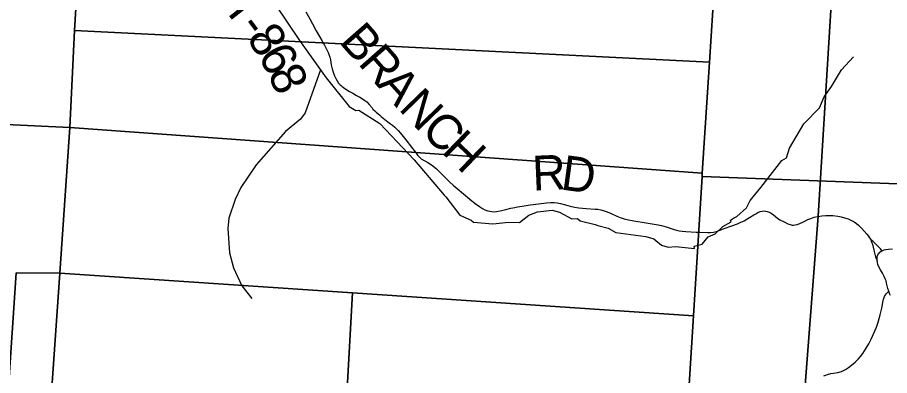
# Model space of a CAD drawing. Extents: x 0 to 34, y 0 to 22.
# Drawn here: x 27.11 to 28.533, y 17.075 to 17.66 of the extents above; entities that cross this region are included whole.
import ezdxf

# ---------------------------------------------------------------- set-up
doc = ezdxf.new("R2010")
doc.units = 0
for name, color, linetype in [('GM_X_County_Road', 7, 'Continuous'), ('GM_X_County_Text', 7, 'Continuous'), ('GM_X_Minor_River', 7, 'Continuous'), ('GM_X_Section', 7, 'Continuous'), ('GM_X_Township_Road', 7, 'Continuous'), ('GM_X_Township_Road_Text', 7, 'Continuous')]:
    doc.layers.add(name, color=color, linetype=linetype)

msp = doc.modelspace()

# ---------------------------------------------------------------- linework, layer by layer
at = {"layer": 'GM_X_County_Road'}
for points in [[(28.5341, 17.2061), (28.5326, 17.2093), (28.5312, 17.2132), (28.5299, 17.2173), (28.5288, 17.222), (28.5278, 17.2264), (28.5268, 17.23), (28.5256, 17.2333), (28.5239, 17.2371), (28.5211, 17.2426), (28.518, 17.2482), (28.5151, 17.2531), (28.5137, 17.2567), (28.5127, 17.2597), (28.5123, 17.2639), (28.5123, 17.2662), (28.5126, 17.2686), (28.513, 17.2708), (28.5136, 17.2722), (28.5146, 17.2739), (28.5158, 17.2754), (28.5169, 17.2767), (28.5184, 17.2779), (28.52, 17.2788), (28.5216, 17.2797), (28.5237, 17.2804), (28.5267, 17.2811), (28.5309, 17.2817), (28.5371, 17.2823)], [(28.4255, 17.0749), (28.4288, 17.0763), (28.4312, 17.0772), (28.4365, 17.0786), (28.4412, 17.0795), (28.4481, 17.0805), (28.4541, 17.0823), (28.4576, 17.0839), (28.4609, 17.0856), (28.4656, 17.0887), (28.4706, 17.0925), (28.4763, 17.0974), (28.4812, 17.1021), (28.4854, 17.1068), (28.4888, 17.1113), (28.4946, 17.1201), (28.4988, 17.1271), (28.5028, 17.1349), (28.5071, 17.1445), (28.5111, 17.1543), (28.514, 17.1625), (28.5158, 17.1685), (28.5174, 17.1745), (28.5197, 17.1855), (28.5223, 17.1979), (28.5229, 17.2003), (28.5236, 17.2026), (28.5243, 17.2043), (28.5252, 17.206), (28.5262, 17.2074), (28.5273, 17.2088), (28.5312, 17.2132)]]:
    msp.add_lwpolyline(points, dxfattribs=at)
at = {"layer": 'GM_X_County_Text'}
for points in [[(27.0716, 14.2873), (27.1862, 14.3829), (27.4012, 14.5633), (27.5003, 14.6738), (27.528, 14.7368), (27.5892, 14.8006), (27.6689, 14.9115), (27.8265, 15.0679), (27.967, 15.1616), (28.1376, 15.2493), (28.2671, 15.2953), (28.2799, 15.2948), (28.2867, 15.4004), (28.3527, 16.4269), (28.3944, 17.0528), (28.4159, 17.3358), (28.4427, 17.7695)], [(28.4427, 17.7695), (28.4159, 17.3358), (28.3944, 17.0528), (28.3527, 16.4269), (28.2867, 15.4004), (28.2799, 15.2948), (28.3301, 15.293), (28.3692, 15.2637), (28.4182, 15.3245), (28.4801, 15.3522), (28.6571, 15.3822), (28.9104, 15.3867), (29.0987, 15.3975), (29.1238, 15.3963), (29.3286, 15.3596), (29.3112, 15.3354), (29.211, 15.3094), (29.213, 15.295), (29.3097, 15.2479), (29.423, 15.2518), (29.4264, 15.2648), (29.4018, 15.2725), (29.4304, 15.2876), (29.5713, 15.2568)]]:
    msp.add_lwpolyline(points, dxfattribs=at)
at = {"layer": 'GM_X_Minor_River'}
for points in [[(27.5304, 17.6805), (27.5698, 17.6221), (27.6133, 17.5614), (27.6508, 17.5147), (27.6618, 17.5079), (27.6667, 17.5083), (27.7011, 17.4867), (27.7571, 17.4275), (27.8059, 17.3699), (27.8086, 17.3672), (27.8313, 17.3373), (27.8498, 17.3289), (27.8536, 17.3259), (27.885, 17.3229), (27.9114, 17.3257), (27.9288, 17.3253), (27.9439, 17.3371), (27.9583, 17.3425), (27.9821, 17.3452), (27.9938, 17.3422), (28.0142, 17.3312), (28.0233, 17.3316), (28.0278, 17.3278), (28.0524, 17.3218), (28.0566, 17.3203), (28.0736, 17.3161), (28.0857, 17.309), (28.1348, 17.3026), (28.1481, 17.2988), (28.1606, 17.2882), (28.1712, 17.2852), (28.1836, 17.286), (28.2142, 17.283), (28.2135, 17.2864), (28.2267, 17.2899), (28.2365, 17.3021), (28.2482, 17.3067), (28.2603, 17.3185), (28.2739, 17.3261), (28.2732, 17.3291), (28.2781, 17.3322), (28.2834, 17.3352), (28.2989, 17.3493), (28.3049, 17.3611), (28.3223, 17.3821), (28.357, 17.4262), (28.3642, 17.4308), (28.3691, 17.4468), (28.3925, 17.486), (28.4182, 17.5123), (28.4257, 17.5302), (28.4378, 17.5469), (28.454, 17.5743), (28.474, 17.5956)], [(27.6038, 17.5746), (27.5792, 17.5043), (27.5714, 17.4936), (27.5469, 17.4739), (27.4992, 17.4192), (27.4742, 17.3824), (27.4646, 17.363), (27.4546, 17.3325), (27.4526, 17.3155), (27.4555, 17.2759), (27.4623, 17.2514), (27.4758, 17.2221), (27.4918, 17.2011)]]:
    msp.add_lwpolyline(points, dxfattribs=at)
at = {"layer": 'GM_X_Section'}
for points in [[(26.2062, 18.5294), (27.254, 18.479), (27.228, 18.0601), (27.2029, 17.6387), (27.1952, 17.4804), (26.5953, 17.5088), (26.1481, 17.5351), (26.1482, 17.5386), (26.1578, 17.7173), (26.1806, 18.1307)], [(29.3481, 18.3713), (29.2849, 17.3606), (28.2266, 17.4004), (28.2269, 17.4056), (28.2386, 17.5871), (28.2659, 18.0119), (28.293, 18.4323)], [(28.2659, 18.0119), (28.2386, 17.5871), (27.2029, 17.6387), (27.228, 18.0601)], [(27.2029, 17.6387), (28.2386, 17.5871), (28.2269, 17.4056), (27.1952, 17.4804)], [(27.1952, 17.4804), (27.1786, 17.2427), (27.1074, 17.2433), (27.0684, 16.6654), (26.5448, 16.6908), (26.5953, 17.5088)], [(28.2269, 17.4056), (28.2266, 17.4004), (28.2124, 17.1731), (27.656, 17.2106), (27.1786, 17.2427), (27.1952, 17.4804)], [(28.2266, 17.4004), (29.2849, 17.3606), (29.2195, 16.3096), (29.0277, 16.3171), (28.8298, 16.3203), (28.6263, 16.3303), (28.4372, 16.34), (28.2749, 16.348), (28.1612, 16.354), (28.2124, 17.1731)], [(27.1786, 17.2427), (27.1198, 16.4014), (27.0508, 16.4046), (27.0684, 16.6654), (27.1074, 17.2433)], [(27.656, 17.2106), (27.6098, 16.3785), (27.1198, 16.4014), (27.1786, 17.2427)], [(28.2124, 17.1731), (28.1612, 16.354), (27.6098, 16.3785), (27.656, 17.2106)]]:
    msp.add_lwpolyline(points, close=True, dxfattribs=at)
at = {"layer": 'GM_X_Township_Road'}
for points in [[(27.5802, 17.6689), (27.5864, 17.6575), (27.5909, 17.6493), (27.5972, 17.6379), (27.6025, 17.6288), (27.6063, 17.6224), (27.6107, 17.6144), (27.6141, 17.6082), (27.6166, 17.6026), (27.6195, 17.595), (27.6206, 17.5908), (27.6217, 17.5825), (27.623, 17.5759), (27.6245, 17.5708), (27.6267, 17.5647), (27.629, 17.56), (27.6312, 17.5563), (27.6336, 17.5528), (27.636, 17.5501), (27.6376, 17.5486), (27.6396, 17.5469), (27.6435, 17.544), (27.6513, 17.5392), (27.6567, 17.5361), (27.6626, 17.5327), (27.668, 17.5296), (27.6744, 17.5259), (27.6766, 17.5245), (27.6794, 17.5219), (27.6832, 17.5177), (27.6881, 17.5121), (27.6897, 17.5103), (27.6929, 17.5073), (27.6951, 17.5052), (27.6984, 17.5024), (27.7007, 17.5004), (27.7031, 17.4984), (27.7059, 17.496), (27.7096, 17.4928), (27.7111, 17.4916), (27.714, 17.4893), (27.718, 17.4864), (27.7215, 17.4838), (27.7254, 17.4806), (27.7282, 17.4781), (27.7309, 17.4752), (27.7345, 17.471), (27.7412, 17.4631), (27.7434, 17.4601), (27.7524, 17.4482), (27.7584, 17.4405)], [(27.7584, 17.4405), (27.7596, 17.4389), (27.761, 17.4369), (27.7621, 17.4352), (27.7633, 17.4338), (27.7649, 17.4323), (27.7665, 17.4306), (27.7684, 17.4292), (27.7792, 17.4229), (27.7849, 17.4192), (27.7899, 17.4156), (27.7932, 17.4128), (27.7985, 17.4076), (27.8046, 17.4014), (27.8143, 17.3918), (27.8211, 17.3856), (27.8271, 17.3805), (27.8476, 17.3635), (27.8563, 17.3565), (27.8633, 17.3513), (27.8685, 17.348), (27.8724, 17.3461), (27.8771, 17.3443), (27.8801, 17.3435), (27.8837, 17.343), (27.8875, 17.3429), (27.8912, 17.3432), (27.8973, 17.3442), (27.9063, 17.3463), (27.9147, 17.3484), (27.9214, 17.3499), (27.9257, 17.3508), (27.933, 17.352), (27.9459, 17.3539), (27.9509, 17.3545), (27.973, 17.3572), (27.9799, 17.3577), (27.9854, 17.3577), (27.9904, 17.3572), (27.9959, 17.3562), (28.0037, 17.3542), (28.0115, 17.352), (28.0187, 17.3504), (28.0255, 17.3492), (28.0316, 17.3485), (28.0378, 17.348), (28.0521, 17.3472), (28.0564, 17.3468), (28.0613, 17.3458), (28.0667, 17.3444), (28.0719, 17.3425), (28.0782, 17.3398), (28.0878, 17.3354), (28.093, 17.3334), (28.0996, 17.3314), (28.1068, 17.3296), (28.1153, 17.3279), (28.1355, 17.3246), (28.1551, 17.3214), (28.1606, 17.3203), (28.1678, 17.3183), (28.1813, 17.3137), (28.1849, 17.3127), (28.1891, 17.3117), (28.194, 17.3109), (28.2002, 17.3103), (28.217, 17.3097), (28.2232, 17.3095), (28.2362, 17.3088), (28.2406, 17.3089), (28.2455, 17.3095), (28.2497, 17.3104), (28.2519, 17.3111), (28.2548, 17.3121), (28.2646, 17.3158), (28.2734, 17.3191), (28.2844, 17.3233), (28.2901, 17.3257), (28.2929, 17.327), (28.2951, 17.3281), (28.3015, 17.3318), (28.3042, 17.3334), (28.311, 17.3376), (28.3142, 17.3394), (28.3174, 17.3413), (28.3213, 17.3431), (28.3248, 17.3439), (28.3279, 17.3441), (28.3303, 17.3439), (28.3327, 17.3433), (28.3361, 17.3421), (28.3393, 17.3403), (28.3432, 17.3375), (28.3499, 17.3321), (28.3534, 17.3298), (28.3604, 17.3261), (28.3664, 17.3232), (28.3705, 17.3218), (28.3735, 17.3211), (28.3759, 17.321), (28.3783, 17.3212), (28.3819, 17.3221), (28.386, 17.3236), (28.3921, 17.3265), (28.3993, 17.3301), (28.4039, 17.3319), (28.4097, 17.3338), (28.4152, 17.335)], [(28.4152, 17.335), (28.4162, 17.3352), (28.4218, 17.3362), (28.4286, 17.3368), (28.4341, 17.3369), (28.4402, 17.3366), (28.4482, 17.3356), (28.4537, 17.3345), (28.459, 17.3331), (28.4649, 17.331), (28.4705, 17.3285), (28.4749, 17.3261), (28.4785, 17.3237), (28.4818, 17.3208), (28.4866, 17.316), (28.4909, 17.3113), (28.4953, 17.3063), (28.4981, 17.303), (28.5, 17.3003), (28.5018, 17.2976), (28.5028, 17.295), (28.5038, 17.2922), (28.5045, 17.2897), (28.5069, 17.28), (28.5089, 17.2716), (28.5103, 17.2676), (28.5123, 17.2639)], [(28.52, 17.2788), (28.5177, 17.2821), (28.5148, 17.285), (28.51, 17.29), (28.5055, 17.2945), (28.5037, 17.2961), (28.5018, 17.2976)]]:
    msp.add_lwpolyline(points, dxfattribs=at)

# ---------------------------------------------------------------- texts
at = {"layer": 'GM_X_Township_Road_Text'}
for s, rotation, p in [('T', 308.0554, (27.4429, 17.6773)), ('-', 306.8199, (27.4689, 17.6441)), ('8', 303.4072, (27.4824, 17.6261)), ('B', 311.3477, (27.6331, 17.6197)), ('R', 311.3464, (27.6639, 17.5846)), ('6', 298.8464, (27.5011, 17.5979)), ('8', 293.6243, (27.5173, 17.5685)), ('A', 311.6869, (27.695, 17.5493)), ('N', 314.0513, (27.73, 17.5101)), ('C', 315.9732, (27.7662, 17.4727)), ('H', 316.1221, (27.7999, 17.4402)), ('R', 2.5241, (27.9507, 17.3771)), ('D', 352.274, (27.9947, 17.3793))]:
    msp.add_text(s, height=0.0568, rotation=rotation, dxfattribs=at).set_placement(p)

doc.saveas('drawing.dxf')
